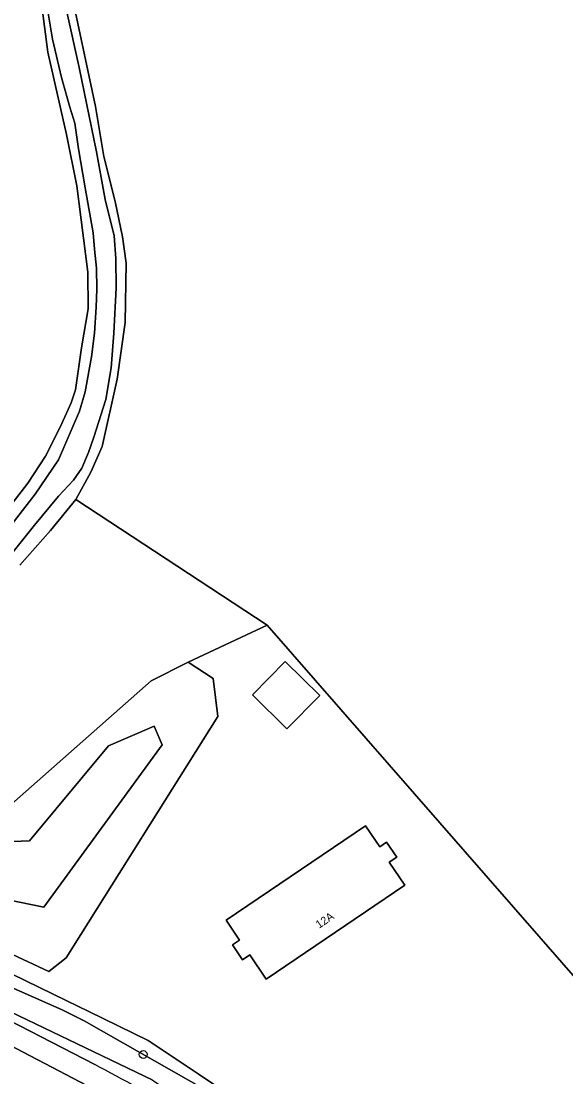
# Model space of a CAD drawing. Extents: x 156502 to 159075, y 384229 to 386100.
# Drawn here: x 158347.3 to 158415.4, y 384300.6 to 384432.5 of the extents above; entities that cross this region are included whole.
import ezdxf

# ---------------------------------------------------------------- set-up
doc = ezdxf.new("R2010")
doc.units = 0
for name, color, linetype in [('IMGEO_Boom', 7, 'Continuous'), ('IMGEO_Fietspad_gesloten', 7, 'Continuous'), ('IMGEO_Gemengd_bos', 7, 'Continuous'), ('IMGEO_Groenvoorziening', 7, 'Continuous'), ('IMGEO_Hek', 7, 'Continuous'), ('IMGEO_Loofbos', 7, 'Continuous'), ('IMGEO_Oever', 7, 'Continuous'), ('IMGEO_Pand', 7, 'Continuous'), ('IMGEO_Pand_nummerreeks', 7, 'Continuous'), ('IMGEO_Waterloop', 7, 'Continuous')]:
    doc.layers.add(name, color=color, linetype=linetype)

msp = doc.modelspace()

# ---------------------------------------------------------------- linework, layer by layer
at = {"layer": 'IMGEO_Boom'}
msp.add_circle((158362.55, 384303.39), 0.489, dxfattribs=at)
at = {"layer": 'IMGEO_Fietspad_gesloten'}
for points in [[(158332.53, 384311.49), (158355.51, 384299.5)], [(158356.49, 384302.12), (158337.53, 384311.89)]]:
    msp.add_lwpolyline(points, dxfattribs=at)
msp.add_arc((158276.81, 384149.4), 172.26, 54.3129, 62.446, dxfattribs=at)
at = {"layer": 'IMGEO_Gemengd_bos'}
for points in [[(158413.39, 384435.74), (158414.06, 384436.79), (158358.67, 384458.19), (158352.23, 384457.81), (158352.77, 384456.53), (158354.62, 384450.04), (158355.17, 384445.31), (158355.63, 384443.04), (158355.3, 384441.2), (158354.64, 384440.35), (158353.55, 384437.91), (158353.4, 384436.77), (158356.6, 384421.83), (158357.61, 384415.61), (158359.05, 384409.98), (158359.95, 384405.56), (158360.43, 384402.26), (158360.28, 384394.83), (158359.31, 384387.76), (158357.44, 384379.37), (158356.01, 384376.14), (158354.11, 384372.75), (158378.03, 384357.05), (158427.25, 384300.73)], [(158340.68, 384365.16), (158348.14, 384374.77), (158350.33, 384378.16), (158352.15, 384381.78), (158353.54, 384384.82), (158354.08, 384386.45), (158354.83, 384391.68), (158355.68, 384396.57), (158355.63, 384401.15), (158354.27, 384411.91), (158352.98, 384418.34), (158350.62, 384428.64), (158349.64, 384436.36)], [(158344.63, 384333.4), (158363.56, 384350.09), (158368.15, 384352.39), (158378.03, 384357.05), (158354.11, 384372.75), (158350.98, 384368.85), (158347.14, 384364.54)]]:
    msp.add_lwpolyline(points, dxfattribs=at)
at = {"layer": 'IMGEO_Groenvoorziening'}
for points in [[(158415.64, 384273.48), (158417.33, 384275.58), (158412.28, 384272.08), (158369.4, 384300.97), (158363.15, 384305.15), (158355.76, 384308.75), (158353, 384310.09), (158330.57, 384320.99), (158316.87, 384327), (158310.78, 384329.66), (158301.4, 384333.78), (158224.68, 384367.19), (158139.02, 384415.66), (158112.87, 384430.01), (158110.98, 384431.04), (158010.38, 384485.78)], [(158192.91, 384390.78), (158246.32, 384360.99), (158345.6, 384316.18), (158350.77, 384313.74), (158352.93, 384315.46), (158371.89, 384345.63), (158371.31, 384350.38), (158368.15, 384352.39), (158363.56, 384350.09), (158344.63, 384333.4), (158337.02, 384334.26), (158320.07, 384341.73), (158308.44, 384351.93), (158199.08, 384402.07)], [(158195.19, 384394.95), (158235.12, 384373.47), (158342.36, 384323.38), (158350.11, 384321.79), (158364.94, 384342.09), (158363.93, 384344.41), (158358.23, 384341.96), (158348.35, 384330.08), (158342.07, 384329.83), (158314.92, 384341.9), (158306.12, 384348.19), (158231.1, 384380.85), (158197.11, 384398.46)], [(158197.11, 384398.46), (158231.1, 384380.85), (158306.12, 384348.19), (158314.92, 384341.9), (158342.07, 384329.83), (158348.35, 384330.08), (158358.23, 384341.96), (158363.93, 384344.41), (158364.94, 384342.09), (158350.11, 384321.79), (158342.36, 384323.38), (158235.12, 384373.47), (158195.19, 384394.95)], [(158189.91, 384385.3), (158231.26, 384362.77), (158262, 384347.66), (158308.14, 384328.47), (158309.24, 384328.81), (158309.86, 384329.55), (158310.45, 384329.73), (158311.52, 384329.27), (158313.2, 384328.32), (158314.64, 384327.47), (158315.24, 384326.95), (158315.09, 384326.08), (158314.98, 384325.5), (158315.51, 384325.27), (158352.43, 384308.98), (158355.18, 384307.6), (158370.62, 384298.81)], [(158363.68, 384300.21), (158325.1, 384318.71), (158313.7, 384323.39), (158312.63, 384323.83), (158309.85, 384324.97), (158308.19, 384325.69), (158306.65, 384326.34), (158238.34, 384355.56), (158204.7, 384373.66)], [(158355.51, 384299.5), (158332.53, 384311.49)], [(158337.53, 384311.89), (158356.49, 384302.12)]]:
    msp.add_lwpolyline(points, dxfattribs=at)
msp.add_arc((158276.81, 384149.4), 172.26, 54.3129, 62.446, dxfattribs=at)
at = {"layer": 'IMGEO_Hek'}
for points in [[(158353, 384310.09), (158330.57, 384320.99), (158316.87, 384327)], [(158355.76, 384308.75), (158353, 384310.09)], [(158363.15, 384305.15), (158355.76, 384308.75)], [(158363.15, 384305.15), (158369.4, 384300.97), (158412.28, 384272.08)]]:
    msp.add_lwpolyline(points, dxfattribs=at)
at = {"layer": 'IMGEO_Loofbos'}
for points in [[(158139.02, 384415.66), (158224.68, 384367.19), (158301.4, 384333.78), (158310.78, 384329.66), (158316.87, 384327), (158330.57, 384320.99), (158353, 384310.09), (158355.76, 384308.75), (158363.15, 384305.15), (158369.4, 384300.97), (158412.28, 384272.08), (158417.33, 384275.58)], [(158427.25, 384300.73), (158378.03, 384357.05), (158368.15, 384352.39), (158371.31, 384350.38), (158371.89, 384345.63), (158352.93, 384315.46), (158350.77, 384313.74), (158345.6, 384316.18), (158246.32, 384360.99), (158192.91, 384390.78)]]:
    msp.add_lwpolyline(points, dxfattribs=at)
for points in [[(158376.22, 384348.33), (158380.31, 384352.47), (158384.61, 384348.23), (158380.52, 384344.08)], [(158377.94, 384312.81), (158375.89, 384315.85), (158374.97, 384315.23), (158373.71, 384317.09), (158374.58, 384317.68), (158372.9, 384320.16), (158390.34, 384331.97), (158392.12, 384329.34), (158392.98, 384329.92), (158394.24, 384328.05), (158393.31, 384327.42), (158395.27, 384324.54)]]:
    msp.add_lwpolyline(points, close=True, dxfattribs=at)
at = {"layer": 'IMGEO_Oever'}
for points in [[(158349.64, 384436.36), (158350.62, 384428.64), (158352.98, 384418.34), (158354.27, 384411.91), (158355.63, 384401.15), (158355.68, 384396.57), (158354.83, 384391.68), (158354.08, 384386.45), (158353.54, 384384.82), (158352.15, 384381.78), (158350.33, 384378.16), (158348.14, 384374.77), (158340.68, 384365.16)], [(158347.14, 384364.54), (158350.98, 384368.85), (158354.11, 384372.75), (158356.01, 384376.14), (158357.44, 384379.37), (158359.31, 384387.76), (158360.28, 384394.83), (158360.43, 384402.26), (158359.95, 384405.56), (158359.05, 384409.98), (158357.61, 384415.61), (158356.6, 384421.83), (158353.4, 384436.77)], [(158353, 384433.67), (158354.55, 384426.72), (158356.7, 384416.17), (158357.79, 384410.2), (158358.9, 384405.68), (158359.11, 384402.83), (158359.17, 384399.2), (158358.89, 384393.52), (158358.56, 384389.19), (158357.88, 384385.23), (158356.38, 384380.54), (158355.72, 384378.62), (158354.89, 384376.65), (158353.84, 384375.14), (158351.96, 384373.17), (158348.96, 384369.54), (158342.57, 384361.61)], [(158344.42, 384367.49), (158349.06, 384373.42), (158351.96, 384377.67), (158354.6, 384383.78), (158355.29, 384386.17), (158356.1, 384390.54), (158356.47, 384393.52), (158356.66, 384396.78), (158356.76, 384399.02), (158356.71, 384401.63), (158356.46, 384404.01), (158356.29, 384406.05), (158355.28, 384411.66), (158354.47, 384416.56), (158354.02, 384419.77), (158353.39, 384421.74), (158352.34, 384425.45), (158351.22, 384430.26), (158350.61, 384433.77)]]:
    msp.add_lwpolyline(points, dxfattribs=at)
at = {"layer": 'IMGEO_Pand'}
for points in [[(158376.22, 384348.33), (158380.52, 384344.08), (158384.61, 384348.23), (158380.31, 384352.47)], [(158395.27, 384324.54), (158393.31, 384327.42), (158394.24, 384328.05), (158392.98, 384329.92), (158392.12, 384329.34), (158390.34, 384331.97), (158372.9, 384320.16), (158374.58, 384317.68), (158373.71, 384317.09), (158374.97, 384315.23), (158375.89, 384315.85), (158377.94, 384312.81)]]:
    msp.add_lwpolyline(points, close=True, dxfattribs=at)
at = {"layer": 'IMGEO_Waterloop'}
for points in [[(158342.57, 384361.61), (158348.96, 384369.54), (158351.96, 384373.17), (158353.84, 384375.14), (158354.89, 384376.65), (158355.72, 384378.62), (158356.38, 384380.54), (158357.88, 384385.23), (158358.56, 384389.19), (158358.89, 384393.52), (158359.17, 384399.2), (158359.11, 384402.83), (158358.9, 384405.68), (158357.79, 384410.2), (158356.7, 384416.17), (158354.55, 384426.72), (158353, 384433.67)], [(158350.61, 384433.77), (158351.22, 384430.26), (158352.34, 384425.45), (158353.39, 384421.74), (158354.02, 384419.77), (158354.47, 384416.56), (158355.28, 384411.66), (158356.29, 384406.05), (158356.46, 384404.01), (158356.71, 384401.63), (158356.76, 384399.02), (158356.66, 384396.78), (158356.47, 384393.52), (158356.1, 384390.54), (158355.29, 384386.17), (158354.6, 384383.78), (158351.96, 384377.67), (158349.06, 384373.42), (158344.42, 384367.49)]]:
    msp.add_lwpolyline(points, dxfattribs=at)
msp.add_lwpolyline([(158314.98, 384325.5), (158314.32, 384324.41), (158313.7, 384323.39), (158325.1, 384318.71), (158363.68, 384300.21), (158383.48, 384286.99), (158384.41, 384287.07), (158384.79, 384287.42), (158384.93, 384289.41), (158370.62, 384298.81), (158355.18, 384307.6), (158352.43, 384308.98), (158315.51, 384325.27)], close=True, dxfattribs=at)

# ---------------------------------------------------------------- texts
at = {"layer": 'IMGEO_Pand_nummerreeks'}
msp.add_text('12A', height=1, rotation=34.0853, dxfattribs=at).set_placement((158384.53, 384319.08))

doc.saveas('drawing.dxf')
